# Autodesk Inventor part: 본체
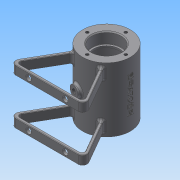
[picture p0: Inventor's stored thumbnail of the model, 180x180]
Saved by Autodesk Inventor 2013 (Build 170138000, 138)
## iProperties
Created: 2016-03
Part Number: 본체
Material: 일반
Document SubType Name: Modeling
Designer: Administrator
Density: 1 g/cm^3
Author: Administrator
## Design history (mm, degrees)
sketch "스케치1"
  geometry: C1 r 26 at (0, 0); 1 further point
  constraints: 1 centre point, 1 coincident
  dimensions: "d0" = 52 diameter of C1
extrude "돌출1" new body sketch "스케치1" distance "d1" = 35; taper "d2" = 0 deg
node "작업 평면1"
sketch "스케치2"
  geometry: L1 (0, 0)-(0, -65); L2 (-42.594, -65)-(42.594, -65); L3 (0, 8.775)-(-42.594, -65); L4 (42.594, -65)-(0, 8.775); C1 r 26 at (0, 0) reference; 1 further point
  constraints: 8 end point, 1 midpoint, 1 perpendicular, 1 vertical
  dimensions: "d4" = 65 distance of L1.end L1.start; "d5" = 30 deg angle of L1 L3; "d7" = 30 deg angle of L4 L1 (derived); "d9" = 85.18802 distance of L2.start L2.end; "d10" = 73.77499 vertical distance of L2.end L3.start
feature "리브1" sketch "스케치2" dims "d11" = 3, "d12" = 10, "d13" = 0, "d14" = 0, "d15" = 1, "d16" = 1
hole "구멍1" diameter "d19" = 28; stored, may be unused: countersink angle "d23" = 90 deg, drill point angle "d25" = 0 deg; dims "d17" = 10, "d18" = 10, "d20" = 6, "d21" = 32, "d22" = 12, "d24" = 14
hole "구멍2" diameter "d28" = 42; stored, may be unused: countersink angle "d32" = 90 deg, drill point angle "d34" = 0 deg; dims "d26" = 10, "d27" = 10, "d29" = 6, "d30" = 32, "d31" = 12, "d33" = 21
sketch "스케치3"
  geometry: C1 r 16 at (0, 0) reference; 1 further point
  constraints: 1 vertical alignment
  dimensions: "d35" = 21 distance of C1.centre point (0, 21)
hole "구멍3" sketch "스케치3" at (0, 21) diameter "d36" = 3.242; stored, may be unused: countersink angle "d40" = 90 deg, drill point angle "d42" = 118 deg; dims "d37" = 8, "d38" = 32, "d39" = 12, "d41" = 10
fillet "모깎기1" dims "d46" = 0.3
fillet "모깎기2" dims "d47" = 3
fillet "모깎기3" dims "d48" = 5
fillet "모깎기4" dims "d49" = 3
fillet "모깎기5" dims "d50" = 0.5
fillet "모깎기6" dims "d51" = 3
node "작업 평면2"
sketch "스케치4"
  geometry: C1 r 5 at (0, 0); 1 further point
  constraints: 1 centre point, 1 coincident
  dimensions: "d53" = 10 diameter of C1
extrude "돌출2" join sketch "스케치4" stored distance "d54" = 35; taper "d55" = 0 deg
hole "구멍4" diameter "d58" = 5.188; stored, may be unused: countersink angle "d62" = 90 deg, drill point angle "d64" = 118 deg; dims "d56" = 10, "d57" = 10, "d59" = 8, "d60" = 32, "d61" = 12, "d63" = 10
sketch "스케치5"
  geometry: L1 (-5, 25.515)-(-5, 29) reference; L2 (-5, 29)-(-2.594, 29) reference; L3 (-2.594, 29)-(-2.594, 20.839) reference; L4 (2.594, 20.839)-(2.594, 29) reference; L5 (2.594, 29)-(5, 29) reference; L6 (5, 29)-(5, 25.515) reference; L7 (0, 0)-(-7.506, -28.012); L8 (0, 0)-(29, 0); A1 r 21 centre (0, 0) between (-2.594, 20.839) and (2.594, 20.839) reference; A2 r 26 centre (0, 0) between (-5, 25.515) and (5, 25.515) reference; 1 further point
  constraints: 4 end point, 1 equal length, 1 horizontal
  dimensions: "d66" = 29 distance of L7.start L7.end; "d67" = 105 deg angle of L7 L8
  node "절단 모서리 투영1"
node "작업 평면3"
sketch "스케치6"
  geometry: C1 r 6 at (0, 0); 1 further point
  constraints: 1 centre point, 1 coincident
  dimensions: "d68" = 12 diameter of C1
extrude "돌출3" join sketch "스케치6" stored distance "d69" = 35; taper "d70" = 0 deg
sketch "스케치7"
  geometry: C1 r 6 at (0, 0) reference; 1 further point
  constraints: 1 coincident
hole "구멍5" sketch "스케치7" at (0, 0) diameter "d71" = 5.188; stored, may be unused: countersink angle "d75" = 90 deg, drill point angle "d77" = 118 deg; dims "d72" = 8, "d73" = 32, "d74" = 12, "d76" = 10
fillet "모깎기8" dims "d78" = 2
node "작업 평면4"
sketch "스케치8"
  geometry: L1 (-65, -29.5)-(-65, -20.5) reference; 2 further points
  constraints: 1 coincident, 1 other
  dimensions: "d79" = 65 distance from line of point (0, 0) L1 (derived)
feature "엠보싱1" sketch "스케치8" dims "d1" = 35, "d30" = 32, "d80" = 0.5, "d81" = 0
sketch "스케치9"
  geometry: L1 (66.206, 50.5)-(70.167, 50.5) reference; L2 (70.718, 50)-(70.718, 41) reference; L3 (70.167, 40.5)-(66.206, 40.5) reference; L4 (64.403, 41)-(64.403, 50) reference; L5 (64.403, 41)-(0, 41) reference; L6 (0, 41)-(0, 50) reference; L7 (0, 50)-(64.403, 50) reference; L8 (-1.803, 40.5)-(-5.763, 40.5) reference; L9 (-6.315, 41)-(-6.315, 50) reference; L10 (-5.763, 50.5)-(-1.803, 50.5) reference; L11 (-1.803, -9.5)-(-5.763, -9.5) reference; L12 (-6.315, -9)-(-6.315, 0) reference; L13 (-5.763, 0.5)-(-1.803, 0.5) reference; L14 (0, 0)-(64.403, 0) reference; L15 (64.403, -9)-(64.403, 0) reference; L16 (70.167, -9.5)-(66.206, -9.5) reference; L17 (70.718, 0)-(70.718, -9) reference; L18 (66.206, 0.5)-(70.167, 0.5) reference; L19 (0, -9)-(0, 0) reference; L20 (64.403, -9)-(0, -9) reference; L21 (0, -9.5)-(64.403, -9.5) reference; 5 further points
  constraints: 2 horizontal alignment, 2 vertical alignment, 16 other
  dimensions: "d82" = 20 horizontal distance of point (32.202, 20.5) point (12.202, 45.5); "d83" = 5 distance from line of L1 point (52.202, 45.5); "d84" = 40 distance of point (52.202, 45.5) point (12.202, 45.5); "d86" = 5 distance from line of point (12.202, -4.5) L21
hole "구멍6" sketch "스케치9" at (12.202, -4.5), (52.202, -4.5), (12.202, 45.5), (52.202, 45.5) diameter "d87" = 6; stored, may be unused: countersink angle "d91" = 90 deg, drill point angle "d93" = 0 deg; dims "d88" = 8, "d89" = 32, "d90" = 12, "d92" = 10
chamfer "모따기1" distance "d94" = 1; stored, may be unused: second distance "d95" = 2, angle "d96" = 45 deg
node "솔리드1"
pattern_circular "원형 패턴1" dims angle "d44" = 360 deg
mirror "대칭1"
node "투영된 루프1"
node "절단 모서리 투영2"
other parameters: "d52" = 29
